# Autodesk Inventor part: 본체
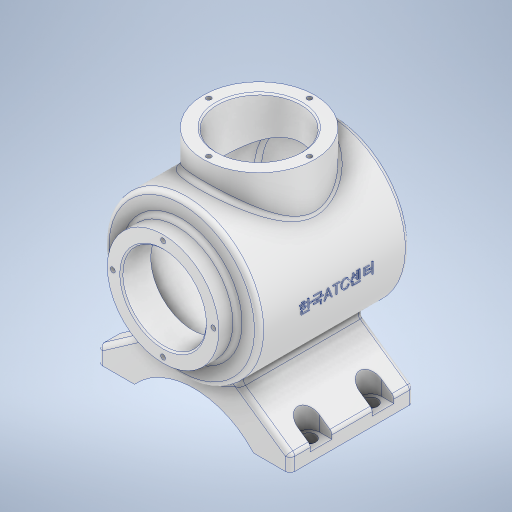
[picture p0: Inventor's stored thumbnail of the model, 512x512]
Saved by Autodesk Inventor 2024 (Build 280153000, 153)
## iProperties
Created: 2023-08
Part Number: 본체
Material: 알루미늄 6061
Document SubType Name: Modeling
Designer: Owner
Density: 2.7 g/cm^3
Appearance: 알루미늄 - 평지
Mass: 1296.71 g
Surface Area: 1060.45 cm^2
Volume: 480.264 cm^3
Author: Owner
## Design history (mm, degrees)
sketch "스케치1"
  geometry: L1 (36, 0)-(36, -12); L2 (36, -12)-(50, -12); L3 (50, -12)-(50, -108.336); L4 (0, 0)-(0, -120); L5 (27, -19)-(43, -19); L6 (43, -19)-(43, -103.887); L7 (27, -19)-(27, 0); L8 (27, 0)-(36, 0); A1 r 113 centre (0, -7) between (0, -120) and (50, -108.336); A2 r 106 centre (0, -7) between (0, -113) and (43, -103.887)
  constraints: 16 end point, 4 perpendicular, 4 point on circle, 2 centre point, 2 point on line, 2 vertical, 1 horizontal alignment, 2 other
  dimensions: "d0" = 100 diameter of L3 L4; "d1" = 72 diameter of L1 L4; "d2" = 113 radius of A1; "d5" = 7 radial gap between concentric circles of A1 A2; "d6" = 54 diameter of L7 L4; "d7" = 120 vertical distance of L4.end L1.start; "d9" = 108 distance from line of L4.end L2
revolve "회전1" sketch "스케치1" stored, may be unused: angle "d8" = 90 deg
node "작업 평면1"
sketch "스케치2"
  geometry: C1 r 36 at (0, -62); 1 further point
  constraints: 1 centre point, 1 vertical alignment
  dimensions: "d11" = 72 diameter of C1; "d12" = 62 distance of point (0, 0) C1.centre
extrude "돌출1" join sketch "스케치2" stored distance "d13" = 10; taper "d14" = 0 deg
sketch "스케치3"
  geometry: C1 r 36 at (0, 0) reference; C2 r 27 at (0, 0); 1 further point
  constraints: 1 centre point, 1 coincident
  dimensions: "d15" = 54 diameter of C2
extrude "돌출2" cut sketch "스케치3" stored distance "d16" = 10; taper "d17" = 0 deg
node "작업 평면2"
sketch "스케치4"
  geometry: L1 (-26.694, -42.278)-(-62, -67); L2 (-62, -67)-(-62, -77); L3 (62, -77)-(62, -67); L4 (62, -67)-(26.694, -42.278); L5 (36, 65)-(-36, 65) reference; L6 (-62, -77)-(-38.5, -77); L7 (38.5, -77)-(62, -77); A1 r 50 centre (0, 0) between (26.694, -42.278) and (-26.694, -42.278) reference; A2 r 52.096 centre (0, -112.096) between (38.5, -77) and (-38.5, -77); 3 further points
  constraints: 12 end point, 5 point on circle, 3 horizontal alignment, 2 equal length, 2 perpendicular, 2 vertical, 2 vertical alignment, 1 centre point
  dimensions: "d19" = 55 deg angle of L3 L4; "d20" = 10 distance of L3.start L3.end; "d21" = 124 distance of L2.end L3.start; "d23" = 77 distance of L7.start L6.end; "d24" = 17 distance of point (0, -77) point (0, -60); "d25" = 142 distance between parallel lines of L7 L5
extrude "돌출3" join sketch "스케치4" distance "d26" = 80; taper "d27" = 0 deg
sketch "스케치5"
  geometry: L1 (23.5, 0)-(23.5, -80) reference; L2 (11.5, 8)-(11.5, -88.336) reference; C1 r 4.5 at (15.5, -20); 2 further points
  constraints: 1 centre point, 1 midpoint
  dimensions: "d33" = 8 distance from line of L1 C1.centre; "d34" = 20 vertical distance of point (23.5, -40) C1.centre; "d35" = 9 diameter of C1
extrude "돌출4" cut sketch "스케치5" distance "d36" = 6; taper "d37" = 0 deg
sketch "스케치6"
  geometry: L1 (0, -7)-(8, -7); L2 (8, 7)-(0, 7); L3 (8, 20)-(8, -60) reference; C1 r 4.5 at (0, 0) reference; A1 r 7 centre (0, 0) between (0, 7) and (0, -7); 3 further points
  constraints: 4 end point, 2 midpoint, 2 point on circle, 2 point on line, 2 tangent, 1 centre point, 1 coincident, 1 horizontal, 1 parallel
  dimensions: "d38" = 14 distance of point (4, -7) point (4, 7)
extrude "돌출5" cut sketch "스케치6" stored distance "d39" = 0; taper "d40" = 0 deg
sketch "스케치7"
  geometry: 2 further points
  constraints: 1 vertical alignment
  dimensions: "d44" = 32.5 distance of point (0, 0) point (0, 32.5)
hole "구멍1" sketch "스케치7" at (0, 32.5) diameter "d45" = 3.242; stored, may be unused: countersink angle "d49" = 90 deg, drill point angle "d51" = 118 deg; dims "d46" = 8, "d47" = 4, "d48" = 2, "d50" = 10
sketch "스케치8"
  geometry: C1 r 27 at (0, 0) reference; 2 further points
  constraints: 1 vertical alignment
  dimensions: "d55" = 32.5 distance of C1.centre point (0, 32.5)
hole "구멍2" sketch "스케치8" at (0, 32.5) diameter "d56" = 3.242; stored, may be unused: countersink angle "d60" = 90 deg, drill point angle "d62" = 118 deg; dims "d57" = 8, "d58" = 4, "d59" = 2, "d61" = 10
node "작업 평면3"
sketch "스케치9"
  geometry: L1 (-36, 60.168)-(36, 60.168) reference; 3 further points
  constraints: 1 midpoint, 1 vertical alignment, 1 other
  dimensions: "d66" = 62 distance from line of L1 point (0, -1.832)
feature "엠보싱1" sketch "스케치9" dims "d15" = 54, "d67" = 0.5, "d68" = 0
fillet "모깎기1" dims "d69" = 3
fillet "모깎기2" dims "d70" = 3
fillet "모깎기3" dims "d71" = 3
fillet "모깎기5" dims "d73" = 3
chamfer "모따기1" distance "d74" = 1; stored, may be unused: second distance "d75" = 2, angle "d76" = 45 deg
node "솔리드1"
mirror "미러1"
pattern_linear "직사각형 패턴1" dims "d43" = 40
pattern_circular "원형 패턴1" dims angle "d53" = 360 deg
pattern_circular "원형 패턴2" dims angle "d64" = 360 deg
feature "A9D066F2-1C7D-4E18-AEED-F7BC21143FA4" dims "d45" = 3.242, "d46" = 8, "d47" = 4, "d48" = 2, "d49" = 90 deg, "d50" = 10, "d51" = 118 deg
other parameters: "d10" = 65, "d22" = 142
